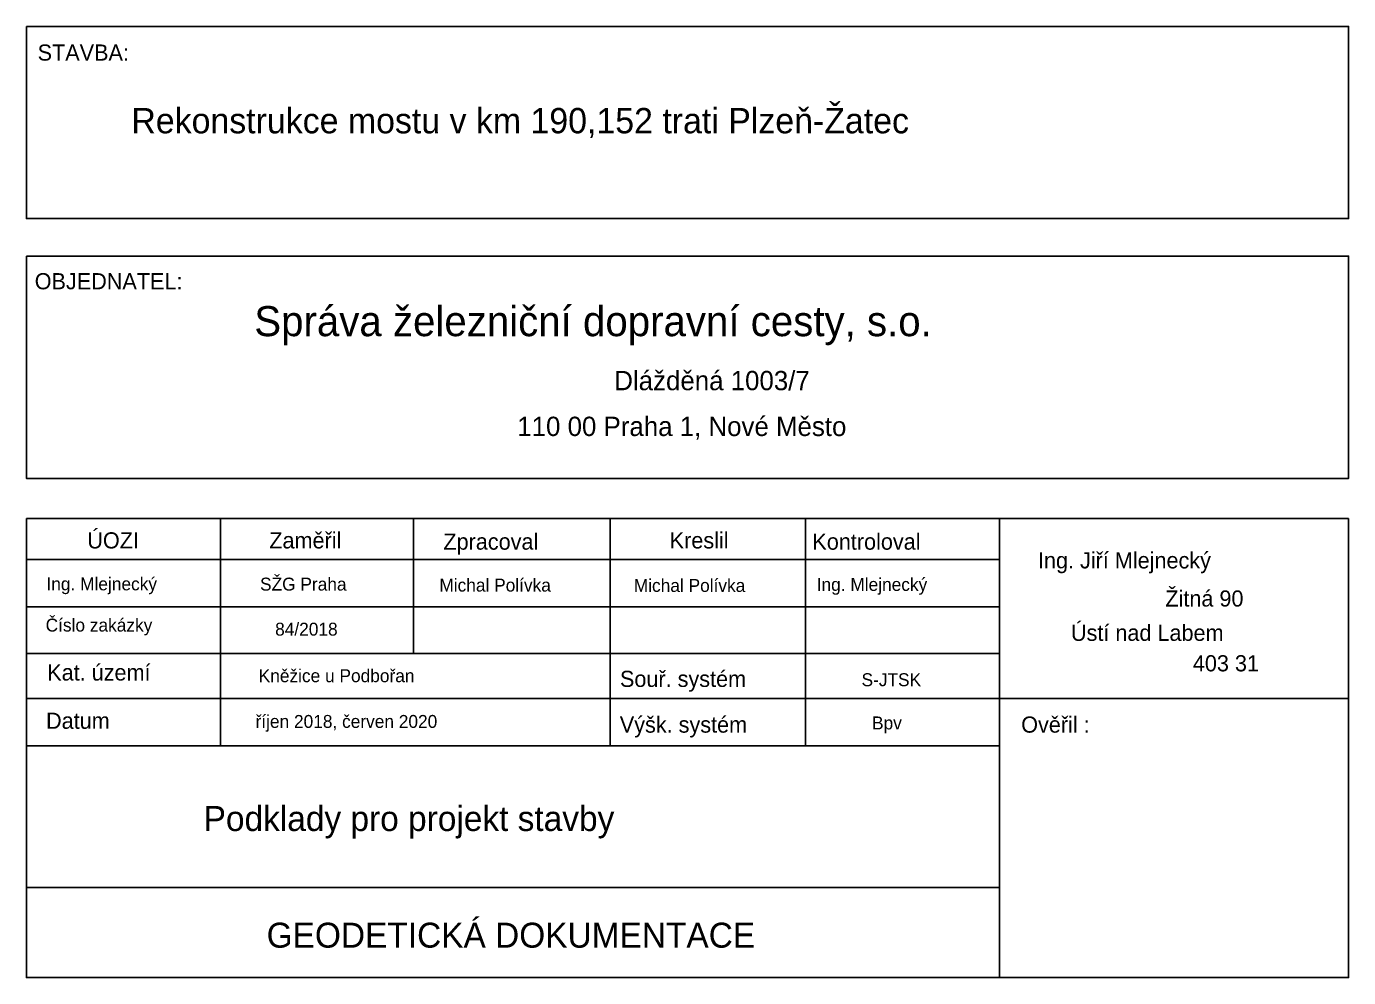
# Model space of a CAD drawing. Extents: x -879530 to -879371, y -1019242 to -1019127.
import ezdxf

# ---------------------------------------------------------------- set-up
doc = ezdxf.new("R2010")
doc.units = 0
doc.layers.add('LEGENDA', color=7, linetype='Continuous')
doc.layers.add('tabulka', color=7, linetype='Continuous')

msp = doc.modelspace()

# ---------------------------------------------------------------- linework, layer by layer
at = {"layer": 'tabulka'}
for p, q in [((-879530.09, -1019186.45), (-879371.44, -1019186.45)), ((-879506.8, -1019186.45), (-879506.8, -1019213.77)), ((-879483.66, -1019186.45), (-879483.66, -1019202.65)), ((-879460.06, -1019186.45), (-879460.06, -1019213.77)), ((-879436.61, -1019186.45), (-879436.61, -1019213.77)), ((-879413.31, -1019241.58), (-879413.31, -1019186.45)), ((-879530.09, -1019191.36), (-879413.31, -1019191.36)), ((-879530.09, -1019197.07), (-879413.31, -1019197.07)), ((-879530.09, -1019202.65), (-879413.31, -1019202.65)), ((-879530.09, -1019208.07), (-879371.44, -1019208.07)), ((-879530.09, -1019213.77), (-879413.31, -1019213.77)), ((-879530.09, -1019230.76), (-879413.31, -1019230.76))]:
    msp.add_line(p, q, dxfattribs=at)
for points in [[(-879530.09, -1019127.36), (-879371.44, -1019127.36), (-879371.44, -1019150.43), (-879530.09, -1019150.43)], [(-879530.09, -1019154.95), (-879371.44, -1019154.95), (-879371.44, -1019181.64), (-879530.09, -1019181.64)]]:
    msp.add_lwpolyline(points, close=True, dxfattribs=at)
msp.add_lwpolyline([(-879371.44, -1019186.45), (-879371.44, -1019241.58), (-879530.09, -1019241.58), (-879530.09, -1019186.45)], dxfattribs=at)

# ---------------------------------------------------------------- texts
at = {"layer": 'LEGENDA'}
msp.add_text('Rekonstrukce mostu v km 190,152 trati Plzeň-Žatec', height=3.04, dxfattribs=at).set_placement((-879517.5, -1019140.2))
at = {"layer": 'tabulka'}
for s, height, p in [('STAVBA:', 1.94, (-879528.75, -1019131.47)), ('OBJEDNATEL:', 1.94, (-879529.1, -1019158.93)), ('Správa železniční dopravní cesty, s.o.', 3.61, (-879502.75, -1019164.56)), ('Dlážděná 1003/7', 2.32, (-879459.55, -1019171.05)), ('110 00 Praha 1, Nové Město', 2.32, (-879471.19, -1019176.55)), ('ÚOZI', 1.94, (-879522.79, -1019190.05)), ('Zaměřil', 1.94, (-879500.95, -1019190.05)), ('Zpracoval', 1.94, (-879480.06, -1019190.2)), ('Kreslil', 1.94, (-879452.9, -1019190.05)), ('Kontroloval', 1.94, (-879435.78, -1019190.2)), ('Ing. Jiří Mlejnecký', 1.94, (-879408.71, -1019192.45)), ('Ing. Mlejnecký', 1.552, (-879527.69, -1019195.08)), ('SŽG Praha', 1.552, (-879502.06, -1019195.11)), ('Michal Polívka', 1.552, (-879480.54, -1019195.23)), ('Michal Polívka', 1.552, (-879457.21, -1019195.27)), ('Ing. Mlejnecký', 1.552, (-879435.26, -1019195.15)), ('Žitná 90', 1.94, (-879393.42, -1019197.03)), ('Číslo zakázky', 1.552, (-879527.79, -1019200.03)), ('84/2018', 1.552, (-879500.25, -1019200.52)), ('Ústí nad Labem', 1.94, (-879404.75, -1019201.15)), ('403 31', 1.94, (-879390.12, -1019204.81)), ('Kat. území', 1.94, (-879527.6, -1019205.91)), ('Kněžice u Podbořan', 1.552, (-879502.22, -1019206.11)), ('Souř. systém', 1.94, (-879458.87, -1019206.68)), ('S-JTSK', 1.552, (-879429.88, -1019206.59)), ('Datum', 1.94, (-879527.74, -1019211.71)), ('říjen 2018, červen 2020', 1.552, (-879502.6, -1019211.6)), ('Výšk. systém', 1.94, (-879458.89, -1019212.17)), ('Bpv', 1.552, (-879428.62, -1019211.78)), ('Ověřil :', 1.94, (-879410.72, -1019212.17)), ('Podklady pro projekt stavby', 3, (-879508.83, -1019223.98)), ('GEODETICKÁ DOKUMENTACE ', 3, (-879501.27, -1019237.99))]:
    msp.add_text(s, height=height, dxfattribs=at).set_placement(p)

doc.saveas('drawing.dxf')
